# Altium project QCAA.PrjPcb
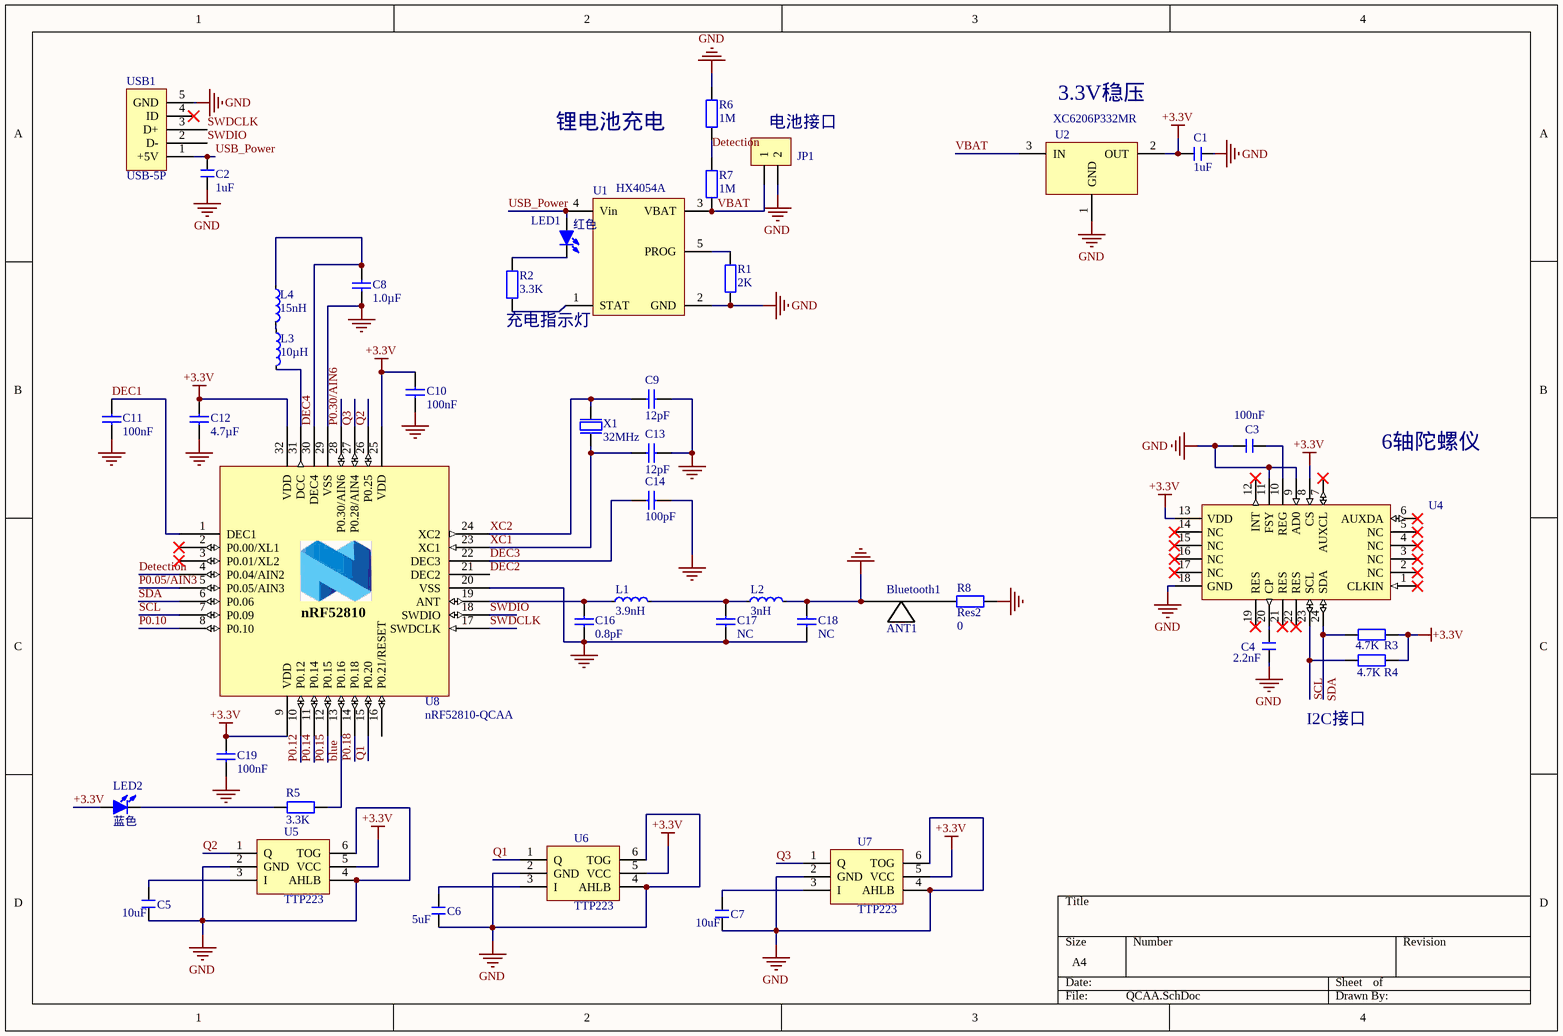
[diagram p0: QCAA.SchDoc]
1 sheet, 43 parts. Net scope: global (net labels, ports and power ports of the same name join across sheets).
Board file: QCAA_7_2.PcbDoc

## Sheet QCAA.SchDoc
size A4

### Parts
Bluetooth1  ANT1  [BLUETOOTH_ANT]
C1  1uF  [C 0402_L]
C2  1uF  [C 0402_L]
C3  100nF  [C 0402_L]
C4  2.2nF  [C 0402_L]
C5  10uF  [C 0402_L]
C6  5uF  [C 0402_L]
C7  10uF  [C 0402_L]
C8  1.0µF  [CAPC1005X04L]
C9  12pF  [CAPC1005X04L]
C10  100nF  [CAPC1005X04L]
C11  100nF  [CAPC1005X04L]
C12  4.7µF  [CAPC1005X04L]
C13  12pF  [CAPC1005X04L]
C14  100pF  [CAPC1005X04L]
C16  0.8pF  [CAPC1005X04L]
C17  NC  [CAPC1005X04L]
C18  NC  [CAPC1005X04L]
C19  100nF  [CAPC1005X04L]
JP1  HDR-1X2  [Power_con]  (value not drawn)
L1  3.9nH  [INDC1005X04L]
L2  3nH  [INDC1005X04L]
L3  10µH  [INDC1005X04L]
L4  15nH  [INDC1005X04L]
LED1  红色  [LED2-0R6X1R0]
LED2  蓝色  [LED2-0R6X1R0]
R1  2K  [R 0402_L]
R2  3.3K  [R 0402_L]
R3  4.7K  [R 0402_L]
R4  4.7K  [R 0402_L]
R5  3.3K  [R 0402_L]
R6  1M  [R 0402_L]
R7  1M  [R 0402_L]
R8  Res2  value 0  [R 0402_L]
U1  HX4054A  [SOT23-5N]
U2  XC6206P332MR  [SOT23-3L]
U4  MPU6050  [MPU6050]  (value not drawn)
U5  TTP223  [SOT23-6L]
U6  TTP223  [SOT23-6L]
U7  TTP223  [SOT23-6L]
U8  nRF52810-QCAA  [Nordic_QFN50P500X500X90-33N]
USB1  USB-5P  [MICRO-USB-SMD_MICROQTJ]
X1  32MHz  [BT-XTAL_2016]

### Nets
+3.3V: C1.2 C10.1 C12.1 C19.1 LED2.1(A) R3.2 R4.2 U2.2(OUT) U4.8(CS) U4.13(VDD) U5.5(VCC) U6.5(VCC) U7.5(VCC) U8.9(VDD) U8.25(VDD) U8.32(VDD)
GND: Bluetooth1.2 C1.1 C2.1 C3.1 C4.1 C5.1 C6.1 C7.1 C8.1 C9.2 C10.2 C11.2 C12.2 C13.2 C14.2 C16.1 C17.1 C18.1 C18.2 C19.2 JP1.2 L2.2 R1.2 R6.2 R8.1 U1.2(GND) U2.1(GND) U4.9(AD0) U4.11(FSY) U4.18(GND) U5.2(GND) U5.4(AHLB) U5.6(TOG) U6.2(GND) U6.4(AHLB) U6.6(TOG) U7.2(GND) U7.4(AHLB) U7.6(TOG) U8.20(VSS) U8.29(VSS) U8.33 USB1.5(GND) X1.2(GND) X1.4(GND)
blue: R5.2 U8.13(P0.16)
DEC1: C11.1 U8.1(DEC1)
DEC2: U8.21(DEC2)
DEC3: C14.1 U8.22(DEC3)
DEC4: C8.2 L4.1 U8.30(DEC4)
Detection: R6.1 R7.2 U8.4(P0.04/AIN2)
P0.05/AIN3: U8.5(P0.05/AIN3)
P0.10: U8.8(P0.10)
P0.12: U8.10(P0.12)
P0.14: U8.11(P0.14)
P0.15: U8.12(P0.15)
P0.18: U8.14(P0.18)
P0.30/AIN6: U8.28(P0.30/AIN6)
Q1: U6.1(Q) U8.15(P0.20)
Q2: U5.1(Q) U8.26(P0.25)
Q3: U7.1(Q) U8.27(P0.28/AIN4)
SCL: R4.1 U4.23(SCL) U8.7(P0.09)
SDA: R3.1 U4.24(SDA) U8.6(P0.06)
SWDCLK: U8.17(SWDCLK) USB1.3(D+)
SWDIO: U8.18(SWDIO) USB1.2(D-)
USB_Power: C2.2 LED1.1(A) U1.4(Vin) USB1.1(+5V)
VBAT: JP1.1 R7.1 U1.3(VBAT) U2.3(IN)
XC1: C13.1 U8.23(XC1) X1.1(inp)
XC2: C9.1 U8.24(XC2) X1.3(out)
NetBluetooth1_1: Bluetooth1.1 R8.2
NetC3_2: C3.2 U4.10(REG)
NetC4_2: C4.2 U4.20(CP)
NetC5_2: C5.2 U5.3(I)
NetC6_2: C6.2 U6.3(I)
NetC7_2: C7.2 U7.3(I)
NetC16_2: C16.2 L1.1 U8.19(ANT)
NetC17_2: C17.2 L1.2 L2.1
NetL3_1: L3.1 L4.2
NetL3_2: L3.2 U8.31(DCC)
NetLED1_2: LED1.2(K) R2.1
NetLED2_2: LED2.2(K) R5.1
NetR1_1: R1.1 U1.5(PROG)
NetR2_2: R2.2 U1.1(STAT)

Not connected (* = marked no-connect by the designer): U4 1(CLKIN)* 2(NC)* 3(NC)* 4(NC)* 5(NC)* 6(AUXDA)* 7(AUXCL)* 12(INT)* 14(NC)* 15(NC)* 16(NC)* 17(NC)* 19(RES)* 21(RES)* 22(RES)*; U8 2(P0.00/XL1)* 3(P0.01/XL2)* 16(P0.21/RESET); USB1 4(ID)*

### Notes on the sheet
- 3.3V稳压
- 锂电池充电
- (near JP1) 电池接口
- (near U1) 充电指示灯
- 6轴陀螺仪
- I2C接口

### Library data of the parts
Bluetooth1 = BLUETOOTH_ANT: PCB板载天线; 版权归属: 源创客
C1-C7 = C: 无极性贴片电容; 版权归属: Fintrol
C8 = C0603-1µ0: Capacitor, X7R, ±10%; Note: 16V
C9 C13 = C0402-12p: Capacitor, NP0, ±2%; Note: 50V
C10 C11 C19 = C0402-100n: Capacitor, X7R, ±10%; Note: 16V
C12 = C0603-4µ7: Capacitor, X5R, ±10%; Note: 6.3V
C14 = C0402-100p: Capacitor, NP0, ±5%; Note: 50V
C16 = C0402-0.8p: Capacitor, NP0, ±5%; Note: 50V
C17 C18 = C0402-0.8p: Capacitor, NP0, ±5%; Value: 0.8pF; Note: 50V
JP1 = Header 2: 2P接插件; 版权归属: 源创客
L1 = L0402-3n9: High frequency chip inductor ±5%
L2 = L0402-3n9: High frequency chip inductor ±5%; Value: 3.9nH
L3 = L0603-10µ: Chip inductor, IDC,min = 50 mA, ±20%
L4 = L0402-15n: High frequency chip inductor ±10%
LED1 LED2 = LED-SMD: 贴片LED; 版权归属: 源创客
R1-R7 = R: 贴片电阻; 版权归属: 源创客
R8 = Res2: Resistor
U1 = MCP73831/2: Li-on Charging IC
U2 = XC6206P332MR: DC-DC Linear IC / Cheap
U4 = MPU6050: Three-axis MEMS IC
U5-U7 = TTP223E-BA6: Touching switch IC
U8 = nRF52810-QCAA: Multi-protocol Bluetooth Low Energy, ANT and 2.4GHz proprietary system-on-chip; Manufacturer: Nordic Semiconductor; Note: nRF52810 - QFN32 5x5 0.5mm pitch
USB1 = USB-5P: 微型USB母座; 版权归属: 源创客
X1 = XTAL_SMD2016_32MHz_8pF_General: XTAL SMD 2016, 32MHz, Cl=8pF, Total Tol: ±40ppm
